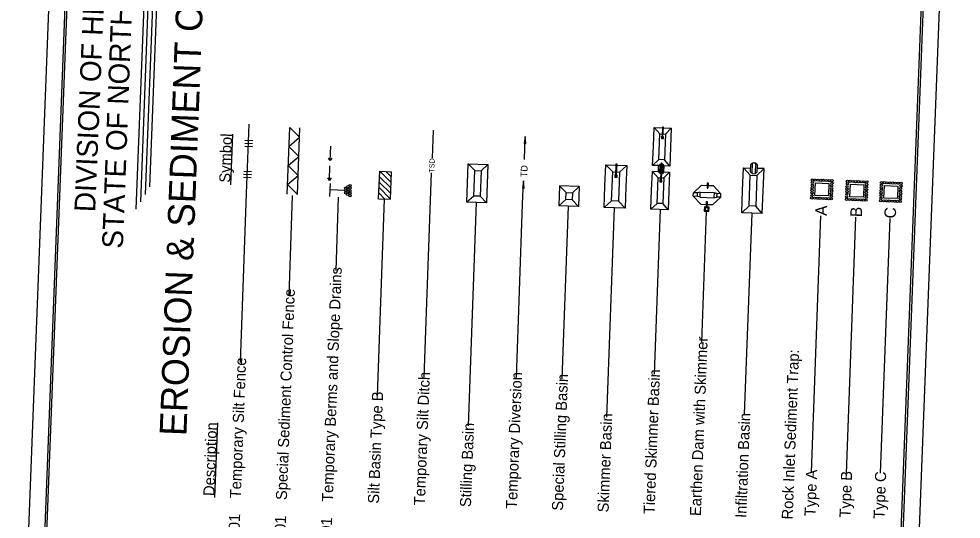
# Model space of a CAD drawing. Extents: x 1654773 to 2116434, y 680831 to 888488.
# Drawn here: x 2109739 to 2115533, y 694040 to 697117 of the extents above; entities that cross this region are included whole.
import ezdxf

# ---------------------------------------------------------------- set-up
doc = ezdxf.new("R2010")
doc.units = 0
for name, color, linetype in [('EC Title Sheet CELL', 7, 'Continuous'), ('Old_Level_1', 7, 'Continuous'), ('Old_Level_12', 7, 'Continuous'), ('Scratch_Level_6', 7, 'Continuous'), ('Sheet Plot Border Inside CELL', 7, 'Continuous'), ('Sheet Plot Border Outside CELL', 7, 'Continuous')]:
    doc.layers.add(name, color=color, linetype=linetype)

msp = doc.modelspace()

# ---------------------------------------------------------------- linework, layer by layer
at = {"layer": 'EC Title Sheet CELL'}
for p, q in [((2111139.6, 696041.9), (2111156, 696469.5)), ((2111388.7, 696037.4), (2111404.7, 696449.4)), ((2111465.6, 696388.3), (2111404.7, 696449.4)), ((2111452.1, 696036), (2111467.9, 696447)), ((2112283.1, 696260.6), (2112289.6, 696431.2)), ((2113640.7, 696331.4), (2113645.2, 696447.6)), ((2113645.2, 696447.6), (2113751.1, 696443.6)), ((2113680.1, 696409.2), (2113645.2, 696447.6)), ((2113695.9, 696391.9), (2113698.3, 696453.3)), ((2113700.2, 696453.2), (2113697.8, 696391.8)), ((2113698.3, 696453.3), (2113700.2, 696453.2)), ((2113714.6, 696407.9), (2113751.1, 696443.6)), ((2113751.2, 696443.7), (2113746.6, 696327.5)), ((2111042.8, 696096), (2111054.6, 696407)), ((2111129.6, 696370.9), (2111177.6, 696369.2)), ((2111400.1, 696332), (2111465.6, 696388.3)), ((2112852.9, 696393.9), (2112847, 696349.7)), ((2112847.5, 696251.5), (2112852.9, 696393.9)), ((2112856.9, 696350.6), (2112852.9, 696393.9)), ((2113674.1, 696251), (2113680.4, 696409.2)), ((2113680.4, 696409.2), (2113714.6, 696407.9)), ((2113690.9, 696392.1), (2113690.4, 696380.9)), ((2113690.4, 696380.9), (2113702.4, 696380.5)), ((2113702.8, 696391.6), (2113690.9, 696392.1)), ((2113692.7, 696390), (2113692.5, 696382.8)), ((2113692.5, 696382.8), (2113700.5, 696382.5)), ((2113700.8, 696389.7), (2113692.7, 696390)), ((2113700.5, 696382.5), (2113700.8, 696389.7)), ((2113702.4, 696380.5), (2113702.8, 696391.6)), ((2113714.6, 696407.9), (2113708.4, 696249.7)), ((2111128.2, 696333.1), (2111176.1, 696331.3)), ((2111128.9, 696352.7), (2111176.7, 696350.9)), ((2111461, 696270.8), (2111400.1, 696332)), ((2112847, 696349.7), (2112856.9, 696350.6)), ((2113636.2, 696215.3), (2113640.7, 696331.4)), ((2113746.6, 696327.5), (2113742.2, 696211.2)), ((2111395.6, 696214.6), (2111461, 696270.8)), ((2111653.7, 696244.9), (2111644.3, 696259.6)), ((2111664.1, 696258.9), (2111653.7, 696244.9)), ((2113674.1, 696251), (2113636.2, 696215.3)), ((2113708.4, 696249.7), (2113674.1, 696251)), ((2113742.2, 696211.2), (2113708.6, 696249.8)), ((2111456.7, 696153.4), (2111395.6, 696214.6)), ((2112494.1, 695989.3), (2112503, 696225.1)), ((2112542.5, 696184.3), (2112503, 696225.1)), ((2112503, 696225.1), (2112623, 696220.5)), ((2112582, 696182.8), (2112623, 696220.5)), ((2112623, 696220.5), (2112613.9, 695984.7)), ((2113343.2, 696088), (2113348.3, 696219.2)), ((2113348.3, 696219.2), (2113477.3, 696214.3)), ((2113391, 696175.8), (2113348.3, 696219.2)), ((2113410.2, 696156.1), (2113413, 696225.4)), ((2113415.3, 696225.3), (2113412.6, 696156)), ((2113413, 696225.4), (2113415.3, 696225.3)), ((2113433, 696174.1), (2113477.3, 696214.3)), ((2113477.4, 696214.4), (2113472.2, 696083.2)), ((2113672.7, 696213.9), (2113636.2, 696215.3)), ((2113671.4, 696176.7), (2113672.7, 696213.9)), ((2113672.7, 696213.9), (2113682.5, 696222.9)), ((2113680.5, 696166.9), (2113682.5, 696222.9)), ((2113682.5, 696222.9), (2113698, 696222.3)), ((2113686.1, 696125.7), (2113690.2, 696231.3)), ((2113692.1, 696231.2), (2113688, 696125.6)), ((2113690.2, 696231.3), (2113692.1, 696231.2)), ((2113698, 696222.3), (2113695.9, 696166.4)), ((2113707, 696212.6), (2113698, 696222.3)), ((2113705.7, 696175.4), (2113707, 696212.6)), ((2113742.2, 696211.2), (2113707, 696212.6)), ((2114189.5, 696061.8), (2114194.9, 696200.2)), ((2114236.5, 696154.5), (2114194.9, 696200.2)), ((2114194.9, 696200.2), (2114238.6, 696198.6)), ((2114237.8, 696176.4), (2114239.4, 696220.7)), ((2114239.4, 696220.7), (2114251, 696231.5)), ((2114248.6, 696164.7), (2114251, 696231.5)), ((2114251, 696231.5), (2114269.4, 696230.8)), ((2114269.4, 696230.8), (2114267, 696164.1)), ((2114280.2, 696219.1), (2114269.4, 696230.8)), ((2114277.6, 696152.9), (2114321.1, 696195.4)), ((2114278.6, 696174.9), (2114280.2, 696219.1)), ((2114321.1, 696195.4), (2114279.3, 696197)), ((2114310.5, 695918.5), (2114321.1, 696195.4)), ((2111120.8, 696142.2), (2111168.8, 696140.3)), ((2111121.5, 696161.8), (2111169.5, 696159.9)), ((2111122.3, 696180.1), (2111170.2, 696178.2)), ((2111391.1, 696097.3), (2111456.7, 696153.4)), ((2111649, 696123.3), (2111639.8, 696139.3)), ((2111649, 696123.3), (2111639.8, 696139.3)), ((2111659.6, 696138.5), (2111649, 696123.3)), ((2111659.6, 696138.5), (2111649, 696123.3)), ((2111951.5, 696010.7), (2111958.1, 696179.4)), ((2111956.8, 696145.4), (2112027.7, 696076)), ((2111958.1, 696179.4), (2112029, 696110)), ((2111958.1, 696179.4), (2112031.4, 696176.7)), ((2111994.8, 696178), (2112030.1, 696142.7)), ((2112025, 696008), (2112031.4, 696176.7)), ((2112271.1, 695998.5), (2112277.6, 696169.1)), ((2113384.1, 695997), (2113391.3, 696175.7)), ((2113391.3, 696175.7), (2113433, 696174.1)), ((2113404.1, 696156.3), (2113403.6, 696143.7)), ((2113403.6, 696143.7), (2113418.2, 696143.2)), ((2113418.7, 696155.8), (2113404.1, 696156.3)), ((2113406.4, 696154), (2113406.1, 696145.9)), ((2113406.1, 696145.9), (2113415.9, 696145.5)), ((2113416.2, 696153.6), (2113406.4, 696154)), ((2113415.9, 696145.5), (2113416.2, 696153.6)), ((2113418.2, 696143.2), (2113418.7, 696155.8)), ((2113433, 696174.1), (2113426, 695995.5)), ((2113630.3, 696062), (2113634.8, 696178.1)), ((2113669.8, 696139.8), (2113634.8, 696178.1)), ((2113671.4, 696176.7), (2113634.8, 696178.1)), ((2113663.7, 695981.5), (2113670.1, 696139.7)), ((2113670.1, 696139.7), (2113704.3, 696138.4)), ((2113671.4, 696176.7), (2113680.5, 696166.9)), ((2113680.5, 696166.9), (2113695.9, 696166.4)), ((2113681.1, 696125.9), (2113680.6, 696114.8)), ((2113693, 696125.4), (2113681.1, 696125.9)), ((2113705.7, 696175.4), (2113695.9, 696166.4)), ((2113704.3, 696138.4), (2113698.1, 695980.3)), ((2113704.3, 696138.4), (2113740.7, 696174.1)), ((2113705.7, 696175.4), (2113740.7, 696174.1)), ((2113740.8, 696174.2), (2113736.3, 696058)), ((2114229.3, 695965.9), (2114236.9, 696154.4)), ((2114236.9, 696154.4), (2114277.6, 696152.9)), ((2114237.8, 696176.4), (2114248.6, 696164.7)), ((2114248.6, 696164.7), (2114267, 696164.1)), ((2114278.6, 696174.9), (2114267, 696164.1)), ((2114277.6, 696152.9), (2114270.2, 695964.4)), ((2111452.1, 696036), (2111391.1, 696097.3)), ((2111652.2, 696023.6), (2111655.4, 696103.4)), ((2111954.2, 696078.7), (2112025, 696008)), ((2111955.6, 696112.8), (2112026.3, 696042)), ((2112618.6, 696106.4), (2112613.9, 695984.7)), ((2112842.3, 696119.4), (2112836.5, 696075.1)), ((2112836.5, 696075.1), (2112846.3, 696074.7)), ((2112836.9, 695976.8), (2112842.3, 696119.4)), ((2112846.3, 696074.7), (2112842.3, 696119.4)), ((2113064.5, 696089.2), (2113059.9, 695967.5)), ((2113184.4, 696084.7), (2113064.5, 696089.2)), ((2113104, 696048.4), (2113064.5, 696089.2)), ((2113143.4, 696047), (2113184.4, 696084.7)), ((2113184.4, 696084.7), (2113179.7, 695962.9)), ((2113338.2, 695956.9), (2113343.2, 696088)), ((2113472.2, 696083.2), (2113467.2, 695951.9)), ((2113680.6, 696114.8), (2113692.6, 696114.3)), ((2113682.9, 696123.9), (2113682.6, 696116.7)), ((2113682.6, 696116.7), (2113690.7, 696116.4)), ((2113691, 696123.6), (2113682.9, 696123.9)), ((2113690.7, 696116.4), (2113691, 696123.6)), ((2113692.6, 696114.3), (2113693, 696125.4)), ((2111102.4, 695003.2), (2111139.6, 696041.9)), ((2111401.4, 695412.1), (2111422.5, 696031.1)), ((2111741.2, 696060.9), (2111655.2, 696064.1)), ((2111690.7, 695569.1), (2111705.4, 696020.2)), ((2111951.5, 696010.7), (2112025, 696008)), ((2111954.3, 696044.7), (2111988.3, 696009.3)), ((2112536.4, 696026.9), (2112494.1, 695989.3)), ((2112536.4, 696026.9), (2112494.1, 695989.3)), ((2112613.9, 695984.7), (2112575.9, 696025.4)), ((2112613.9, 695984.7), (2112575.9, 696025.4)), ((2113625.9, 695945.9), (2113630.3, 696062)), ((2113736.3, 696058), (2113731.8, 695941.7)), ((2114184.2, 695923.4), (2114189.5, 696061.8)), ((2111944.5, 694799), (2111988.3, 696009.3)), ((2112232.2, 694913.6), (2112271.1, 695998.5)), ((2112613.9, 695984.7), (2112494.1, 695989.3)), ((2112613.9, 695984.7), (2112494.1, 695989.3)), ((2112503.1, 694613), (2112554, 695987)), ((2112798.7, 694911.3), (2112836.9, 695976.8)), ((2113102.2, 696005.2), (2113059.9, 695967.5)), ((2113179.7, 695962.9), (2113059.9, 695967.5)), ((2113080.4, 694902.9), (2113119.8, 695965.2)), ((2113179.7, 695962.9), (2113141.7, 696003.6)), ((2113384.1, 695997), (2113338.2, 695956.9)), ((2113467.2, 695951.9), (2113338.2, 695956.9)), ((2113355, 694667.4), (2113402.7, 695954.4)), ((2113426, 695995.5), (2113384.1, 695997)), ((2113467.2, 695951.9), (2113426.1, 695995.6)), ((2113663.7, 695981.5), (2113625.9, 695945.9)), ((2113698.1, 695980.3), (2113663.7, 695981.5)), ((2113731.8, 695941.7), (2113698.2, 695980.3)), ((2114229.3, 695965.9), (2114184.2, 695923.4)), ((2114270.2, 695964.4), (2114229.3, 695965.9)), ((2114310.5, 695918.5), (2114270.4, 695964.5)), ((2113731.8, 695941.7), (2113625.9, 695945.9)), ((2113648, 694930.8), (2113685.6, 695943.5)), ((2113938, 695127.6), (2113967.9, 695932.7)), ((2114310.5, 695918.5), (2114184.2, 695923.4)), ((2114201.5, 694685.7), (2114247.3, 695921)), ((2114613, 694328.9), (2114671.4, 695905.7)), ((2114828.2, 694320.1), (2114886.6, 695897.4)), ((2115037.7, 694322.6), (2115095.8, 695889.4)), ((2110945.1, 694172.7), (2110962.7, 694633))]:
    msp.add_line(p, q, dxfattribs=at)
for points in [[(2111653.7, 696244.9), (2111657, 696333.8)], [(2111649, 696123.3), (2111652.4, 696212.2)], [(2111649, 696123.3), (2111652.4, 696212.2)]]:
    msp.add_lwpolyline(points, dxfattribs=at)
for points in [[(2112575.9, 696025.4), (2112536.4, 696026.9), (2112542.5, 696184.3), (2112582, 696182.8)], [(2114634.3, 696030.2), (2114637.3, 696107.5), (2114720.4, 696104.2), (2114717.6, 696028.3)], [(2114849.5, 696022), (2114852.4, 696099.2), (2114934.3, 696096.2), (2114932.7, 696020.1)], [(2115058.6, 696013.9), (2115061.5, 696091), (2115144.7, 696087.9), (2115141.9, 696012)], [(2113141.7, 696003.6), (2113102.2, 696005.2), (2113104, 696048.4), (2113143.4, 696047)]]:
    msp.add_lwpolyline(points, close=True, dxfattribs=at)
for centre, major_axis in [((2114618.9, 696125.8), (7.07, -0.27)), ((2114636, 696125.1), (7.07, -0.27)), ((2114653.2, 696124.4), (7.07, -0.27)), ((2114670.3, 696123.8), (7.07, -0.27)), ((2114687.4, 696123.1), (7.07, -0.27)), ((2114704.6, 696122.5), (7.07, -0.27)), ((2114721.7, 696121.8), (7.07, -0.27)), ((2114738.8, 696121.2), (7.07, -0.27)), ((2111749.2, 696075.6), (-7.33, 0.28)), ((2111762.4, 696084.1), (-7.33, 0.28)), ((2111763, 696067.3), (-7.33, 0.28)), ((2111775.6, 696076.4), (-7.33, 0.28)), ((2111776.2, 696091.3), (-7.33, 0.28)), ((2114616.5, 696062.2), (7.07, -0.27)), ((2114617.1, 696078.1), (7.07, -0.27)), ((2114617.7, 696094), (7.07, -0.27)), ((2114618.3, 696109.9), (7.07, -0.27)), ((2114737, 696073.5), (7.07, -0.27)), ((2114737.6, 696089.4), (7.07, -0.27)), ((2114738.2, 696105.3), (7.07, -0.27)), ((2114831.5, 696070), (7.07, -0.27)), ((2114832.2, 696085.8), (7.07, -0.27)), ((2114832.8, 696101.7), (7.07, -0.27)), ((2114833.4, 696117.6), (7.07, -0.27)), ((2114850.5, 696117), (7.07, -0.27)), ((2114867.6, 696116.3), (7.07, -0.27)), ((2114884.8, 696115.6), (7.07, -0.27)), ((2114901.9, 696115), (7.07, -0.27)), ((2114919, 696114.3), (7.07, -0.27)), ((2114936.2, 696113.7), (7.07, -0.27)), ((2114951.5, 696065.4), (7.07, -0.27)), ((2114952.1, 696081.2), (7.07, -0.27)), ((2114952.7, 696097.1), (7.07, -0.27)), ((2114953.3, 696113), (7.07, -0.27)), ((2115041.4, 696061.8), (7.07, -0.27)), ((2115042, 696077.7), (7.07, -0.27)), ((2115042.6, 696093.6), (7.07, -0.27)), ((2115043.2, 696109.5), (7.07, -0.27)), ((2115060.3, 696108.8), (7.07, -0.27)), ((2115077.5, 696108.2), (7.07, -0.27)), ((2115094.6, 696107.5), (7.07, -0.27)), ((2115111.7, 696106.8), (7.07, -0.27)), ((2115128.8, 696106.2), (7.07, -0.27)), ((2115146, 696105.5), (7.07, -0.27)), ((2115161.9, 696073.1), (7.07, -0.27)), ((2115162.5, 696089), (7.07, -0.27)), ((2115163.1, 696104.9), (7.07, -0.27)), ((2111748.6, 696060.7), (-7.33, 0.28)), ((2111748.7, 696046.4), (-7.33, 0.28)), ((2111761.9, 696037.5), (-7.33, 0.28)), ((2111762.5, 696053), (-7.33, 0.28)), ((2111775.1, 696028.7), (-7.33, 0.28)), ((2111775.7, 696044.2), (-7.33, 0.28)), ((2111776.2, 696059.1), (-7.33, 0.28)), ((2114614.6, 696014.6), (7.07, -0.27)), ((2114615.2, 696030.4), (7.07, -0.27)), ((2114615.9, 696046.3), (7.07, -0.27)), ((2114631.8, 696013.9), (7.07, -0.27)), ((2114648.9, 696013.2), (7.07, -0.27)), ((2114666, 696012.6), (7.07, -0.27)), ((2114683.2, 696011.9), (7.07, -0.27)), ((2114700.3, 696011.3), (7.07, -0.27)), ((2114717.4, 696010.6), (7.07, -0.27)), ((2114734.5, 696010), (7.07, -0.27)), ((2114735.2, 696025.8), (7.07, -0.27)), ((2114735.8, 696041.7), (7.07, -0.27)), ((2114736.4, 696057.6), (7.07, -0.27)), ((2114829.1, 696006.4), (7.07, -0.27)), ((2114829.7, 696022.3), (7.07, -0.27)), ((2114830.3, 696038.2), (7.07, -0.27)), ((2114830.9, 696054.1), (7.07, -0.27)), ((2114846.2, 696005.8), (7.07, -0.27)), ((2114863.4, 696005.1), (7.07, -0.27)), ((2114880.5, 696004.4), (7.07, -0.27)), ((2114897.6, 696003.8), (7.07, -0.27)), ((2114949.6, 696017.7), (7.07, -0.27)), ((2114950.2, 696033.6), (7.07, -0.27)), ((2114950.8, 696049.5), (7.07, -0.27)), ((2115039.5, 696014.2), (7.07, -0.27)), ((2115040.1, 696030), (7.07, -0.27)), ((2115040.8, 696045.9), (7.07, -0.27)), ((2115159.4, 696009.6), (7.07, -0.27)), ((2115160.1, 696025.4), (7.07, -0.27)), ((2115160.7, 696041.3), (7.07, -0.27)), ((2115161.3, 696057.2), (7.07, -0.27)), ((2114914.8, 696003.1), (7.07, -0.27)), ((2114931.9, 696002.5), (7.07, -0.27)), ((2114949, 696001.8), (7.07, -0.27)), ((2115038.9, 695998.3), (7.07, -0.27)), ((2115056.1, 695997.6), (7.07, -0.27)), ((2115073.2, 695997), (7.07, -0.27)), ((2115090.3, 695996.3), (7.07, -0.27)), ((2115107.4, 695995.6), (7.07, -0.27)), ((2115124.6, 695995), (7.07, -0.27)), ((2115141.7, 695994.3), (7.07, -0.27)), ((2115158.8, 695993.7), (7.07, -0.27))]:
    msp.add_ellipse(centre, major_axis=major_axis, ratio=0.927398, dxfattribs=at)
at = {"layer": 'Old_Level_1'}
for p, q in [((2110461.5, 695946), (2110542.3, 698050.4)), ((2110489.1, 695991.1), (2110566.2, 698001.3)), ((2110518, 696036.1), (2110591.5, 697952.1)), ((2110544.2, 696083.4), (2110614.1, 697903))]:
    msp.add_line(p, q, dxfattribs=at)
at = {"layer": 'Scratch_Level_6'}
for p, q in [((2113886.8, 696047.4), (2113936.5, 696093.5)), ((2113936.5, 696093.5), (2113971.9, 696092.1)), ((2113972.5, 696107.6), (2113971.2, 696075.4)), ((2113971.2, 696075.4), (2113975.8, 696075.2)), ((2113972.5, 696107.6), (2113977.1, 696107.4)), ((2113977.1, 696107.4), (2113975.8, 696075.2)), ((2113976.5, 696092), (2114009, 696090.7)), ((2114009, 696090.7), (2114056, 696040.8)), ((2113886, 696026), (2113886.8, 696047.4)), ((2113911.2, 696025), (2113886, 696026)), ((2113886, 696026), (2113932, 695977.1)), ((2113912, 696046.4), (2113886.8, 696047.4)), ((2113911.2, 696025), (2113912, 696046.4)), ((2113927.8, 696019.3), (2113911.2, 696025)), ((2113929, 696051.7), (2113912, 696046.4)), ((2113927.8, 696019.3), (2113929, 696051.7)), ((2113927.8, 696019.3), (2114012.9, 696016.1)), ((2113929, 696051.7), (2114014.2, 696048.5)), ((2114006.5, 695974.3), (2114055.1, 696019.4)), ((2114014.2, 696048.6), (2114012.9, 696016.1)), ((2114012.9, 696016.1), (2114029.9, 696020.4)), ((2114014.2, 696048.6), (2114030.8, 696041.8)), ((2114030.8, 696041.8), (2114029.9, 696020.4)), ((2114055.1, 696019.4), (2114029.9, 696020.4)), ((2114056, 696040.8), (2114030.8, 696041.8)), ((2114055.1, 696019.4), (2114056, 696040.8)), ((2113932, 695977.1), (2113967.2, 695975.8)), ((2113954.5, 695960.1), (2113953.4, 695933.2)), ((2113983.4, 695959), (2113954.5, 695960.1)), ((2113959, 695955.2), (2113958.3, 695937.8)), ((2113978.4, 695954.4), (2113959, 695955.2)), ((2113966.6, 695959.6), (2113967.9, 695992.6)), ((2113967.9, 695992.6), (2113972.6, 695992.4)), ((2113971.3, 695959.4), (2113972.6, 695992.4)), ((2113971.9, 695975.6), (2114006.5, 695974.3)), ((2113977.8, 695937), (2113978.4, 695954.4)), ((2113982.3, 695932.1), (2113983.4, 695959)), ((2113953.4, 695933.2), (2113982.3, 695932.1)), ((2113958.3, 695937.8), (2113977.8, 695937))]:
    msp.add_line(p, q, dxfattribs=at)
msp.add_lwpolyline([(2110171.4, 700758.7), (2109883.7, 693264.2), (2115129.9, 693062.9), (2115417.5, 700557.4)], close=True, dxfattribs=at)
at = {"layer": 'Sheet Plot Border Inside CELL'}
msp.add_lwpolyline([(2115112.9, 692295.5), (2115432.4, 700619.3), (2110161.3, 700821.7), (2109841.8, 692497.8)], close=True, dxfattribs=at)
at = {"layer": 'Sheet Plot Border Outside CELL'}
msp.add_lwpolyline([(2115210.4, 692226.7), (2115533.2, 700638), (2110062.2, 700848), (2109739.4, 692436.7)], close=True, dxfattribs=at)

# ---------------------------------------------------------------- texts
at = {"layer": 'EC Title Sheet CELL'}
for s, height, p in [('Symbol', 67.83, (2111039, 696107.9)), ('TSD', 31.7, (2112293.2, 696171)), ('TD', 41.14, (2112865.1, 696142.7)), ('A', 71.4, (2114707.1, 695904.3)), ('B', 71.4, (2114922.3, 695896.1)), ('C', 71.4, (2115131.4, 695888)), ('Temporary Berms and Slope Drains ', 67.733, (2111669.9, 694144.9)), ('Special Sediment Control Fence', 67.828, (2111387.1, 694155.8)), ('Earthen Dam with Skimmer', 67.828, (2113932.7, 694057.7)), ('Temporary Silt Fence', 67.828, (2111104.2, 694166.6)), ('Rock Inlet Sediment Trap:', 67.733, (2114497.2, 694036.4)), ('Temporary Silt Ditch', 67.828, (2112235.8, 694123.2)), ('Temporary Diversion', 67.855, (2112801.6, 694101.5)), ('Special Stilling Basin', 67.828, (2113084.4, 694090.6)), ('Tiered Skimmer Basin', 67.828, (2113647.9, 694069)), ('Silt Basin Type B', 67.828, (2111952.9, 694134.1)), ('Skimmer Basin', 67.828, (2113365, 694079.9)), ('Infiltration Basin', 67.828, (2114212, 694046.4)), ('Description', 67.828, (2110941.1, 694180.8)), ('Stilling Basin', 67.828, (2112518.7, 694112.4)), (' Type A', 67.83, (2114636.1, 694031.1)), (' Type B', 67.83, (2114851.3, 694022.8)), (' Type C', 67.83, (2115060.4, 694014.8)), ('1605.01', 67.74, (2111087.9, 693743.9)), ('1606.01', 67.74, (2111370.8, 693733.1)), ('1622.01', 67.74, (2111653.7, 693722.2))]:
    msp.add_text(s, height=height, rotation=87.80201, dxfattribs=at).set_placement(p)
at = {"layer": 'Old_Level_1'}
for s, height, p in [('EROSION & SEDIMENT CONTROL LEGEND', 164.827, (2110769.3, 694549.1)), ('STATE OF NORTH CAROLINA', 128.198, (2110378.7, 695701.8))]:
    msp.add_text(s, height=height, rotation=87.802, dxfattribs=at).set_placement(p)
at = {"layer": 'Old_Level_12'}
msp.add_text(' DIVISION OF HIGHWAYS', height=128.198, rotation=87.57192, dxfattribs=at).set_placement((2110206.5, 695878.5))

doc.saveas('drawing.dxf')
